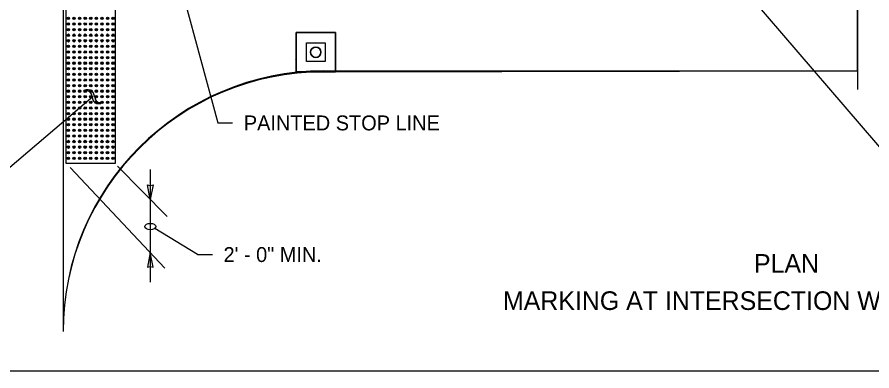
# Model space of a CAD drawing. Extents: x 99862 to 103151, y 100000 to 102076.
# Drawn here: x 100350 to 101268, y 100000 to 100380 of the extents above; entities that cross this region are included whole.
import ezdxf

# ---------------------------------------------------------------- set-up
doc = ezdxf.new("R2010")
doc.units = 0
for name, color, linetype in [('Level 1', 7, 'Continuous'), ('Level 15', 7, 'Continuous'), ('Level 2', 7, 'Continuous'), ('Level 20', 7, 'Continuous'), ('Level 22', 7, 'Continuous'), ('Level 3', 7, 'Continuous'), ('Level 5', 7, 'Continuous')]:
    doc.layers.add(name, color=color, linetype=linetype)

msp = doc.modelspace()

# ---------------------------------------------------------------- linework, layer by layer
at = {"layer": 'Level 1'}
for points in [[(99862, 99999.5), (103151, 99999.5), (103151, 102075.5), (99862, 102075.5)], [(100649.56, 100362.98), (100691.88, 100362.98), (100691.88, 100320.94), (100649.56, 100320.94)], [(100660.76, 100351.9), (100680.76, 100351.9), (100680.76, 100331.9), (100660.76, 100331.9)]]:
    msp.add_lwpolyline(points, close=True, dxfattribs=at)
for points in [[(100649.56, 100362.98), (100649.56, 100320.94), (100691.88, 100320.94), (100691.88, 100362.98), (100649.56, 100362.98)], [(100660.76, 100331.9), (100660.76, 100351.9), (100680.76, 100351.9), (100680.76, 100331.9), (100660.76, 100331.9)]]:
    msp.add_lwpolyline(points, dxfattribs=at)
msp.add_circle((100670.76, 100341.9), 5.59, dxfattribs=at)
at = {"layer": 'Level 15'}
for p, q in [((100507.67, 100479.69), (100565.51, 100265.94)), ((101089.52, 100457.2), (101313.09, 100196.3)), ((100422.68, 100300.39), (100424.27, 100301.77)), ((100425.11, 100300.33), (100422.68, 100300.39)), ((100424.27, 100301.77), (100426.26, 100301.9)), ((100426.81, 100300.03), (100425.11, 100300.33)), ((100426.26, 100301.9), (100428.03, 100301.6)), ((100428.05, 100299.45), (100426.81, 100300.03)), ((100428.03, 100301.6), (100429.57, 100300.87)), ((100429.05, 100298.58), (100428.05, 100299.45)), ((100430.02, 100296.92), (100429.05, 100298.58)), ((100429.57, 100300.87), (100430.88, 100299.7)), ((100430.88, 100299.7), (100432.29, 100297.37)), ((100431.78, 100294.2), (100329.7, 100207.59)), ((100430.73, 100294.47), (100430.02, 100296.92)), ((100431.77, 100290.51), (100430.73, 100294.47)), ((100433.09, 100288.43), (100431.77, 100290.51)), ((100432.29, 100297.37), (100433.49, 100293.12)), ((100433.49, 100293.12), (100434.16, 100290.79)), ((100434.16, 100290.79), (100434.95, 100289.51)), ((100434.95, 100289.51), (100436.06, 100288.63)), ((100434.33, 100287.32), (100433.09, 100288.43)), ((100435.79, 100286.63), (100434.33, 100287.32)), ((100437.54, 100286.32), (100435.79, 100286.63)), ((100436.06, 100288.63), (100437.59, 100288.04)), ((100439.69, 100286.37), (100437.54, 100286.32)), ((100437.59, 100288.04), (100441.28, 100287.76)), ((100441.28, 100287.76), (100439.68, 100286.37)), ((100565.51, 100265.94), (100581.51, 100265.94)), ((100407.2, 100218.06), (100508.8, 100109.97)), ((100457.85, 100219.34), (100511.1, 100165.26)), ((100493.13, 100216.07), (100493.13, 100184.21)), ((100493.13, 100183.61), (100493.13, 100125.5)), ((100543.71, 100124.51), (100497.79, 100152.56)), ((100493.13, 100126.59), (100493.13, 100094.73)), ((100543.71, 100124.51), (100559.71, 100124.51))]:
    msp.add_line(p, q, dxfattribs=at)
msp.add_lwpolyline([(101252.33, 100621.81), (101252.33, 100477.35), (101267.81, 100477.35), (101236.84, 100446.37), (101252.33, 100446.37), (101252.33, 100301.81)], dxfattribs=at)
for points in [[(100493.13, 100183.61), (100490.04, 100199.34), (100493.13, 100198.61), (100496.21, 100199.34)], [(100493.13, 100126.59), (100490.04, 100110.86), (100493.13, 100111.59), (100496.21, 100110.86)]]:
    msp.add_lwpolyline(points, close=True, dxfattribs=at)
msp.add_ellipse((100493.13, 100154.56), major_axis=(-6, 0), ratio=0.57735, dxfattribs=at)
at = {"layer": 'Level 2'}
for p, q in [((100399.47, 100881.81), (100399.47, 100041.81)), ((100399.47, 100881.81), (100399.47, 100041.81)), ((100679.47, 100321.81), (101252.2, 100321.81)), ((100679.47, 100320.79), (101252.2, 100321.81)), ((100679.47, 100321.81), (101251.39, 100321.81))]:
    msp.add_line(p, q, dxfattribs=at)
msp.add_lwpolyline([(101252.2, 100321.81), (101252.2, 100446.2), (101236.71, 100446.2), (101240.44, 100449.93)], dxfattribs=at)
for centre, radius, start, end in [((100679.47, 100041.81), 280, 90, 180), ((100678.97, 100041.3), 279.49, 89.89566, 179.89566)]:
    msp.add_arc(centre, radius, start, end, dxfattribs=at)
at = {"layer": 'Level 22'}
msp.add_line((100648.58, 100334.27), (100648.58, 100334.27), dxfattribs=at)
at = {"layer": 'Level 3'}
for start, end in [(0, 180), (180, 0)]:
    msp.add_arc((100670.76, 100341.9), 5.59, start, end, dxfattribs=at)
at = {"layer": 'Level 5'}
for p, q in [((100402.9, 100222.47), (100402.9, 100446.36)), ((100455.2, 100446.36), (100455.2, 100222.47)), ((100455.2, 100222.47), (100402.9, 100222.47))]:
    msp.add_line(p, q, dxfattribs=at)
for centre, major_axis in [((100405.21, 100378.25), (0, 1.31)), ((100405.21, 100372.23), (0, 1.31)), ((100405.17, 100378.25), (0, -0.755)), ((100405.17, 100372.23), (0, -0.755)), ((100411.21, 100378.25), (0, 1.31)), ((100411.21, 100372.23), (0, 1.31)), ((100411.17, 100378.25), (0, -0.755)), ((100411.17, 100372.23), (0, -0.755)), ((100417.21, 100378.25), (0, 1.31)), ((100417.21, 100372.23), (0, 1.31)), ((100417.17, 100378.25), (0, -0.755)), ((100417.17, 100372.23), (0, -0.755)), ((100423.21, 100378.25), (0, 1.31)), ((100423.21, 100372.23), (0, 1.31)), ((100423.17, 100378.25), (0, -0.755)), ((100423.17, 100372.23), (0, -0.755)), ((100429.21, 100378.25), (0, 1.31)), ((100429.21, 100372.23), (0, 1.31)), ((100429.17, 100378.25), (0, -0.755)), ((100429.17, 100372.23), (0, -0.755)), ((100435.21, 100378.25), (0, 1.31)), ((100435.21, 100372.23), (0, 1.31)), ((100435.17, 100378.25), (0, -0.755)), ((100435.17, 100372.23), (0, -0.755)), ((100441.21, 100378.25), (0, 1.31)), ((100441.21, 100372.23), (0, 1.31)), ((100441.17, 100378.25), (0, -0.755)), ((100441.17, 100372.23), (0, -0.755)), ((100447.21, 100378.25), (0, 1.31)), ((100447.21, 100372.23), (0, 1.31)), ((100447.17, 100378.25), (0, -0.755)), ((100447.17, 100372.23), (0, -0.755)), ((100453.21, 100378.25), (0, 1.31)), ((100453.21, 100372.23), (0, 1.31)), ((100453.17, 100378.25), (0, -0.755)), ((100453.17, 100372.23), (0, -0.755)), ((100405.21, 100366.22), (0, 1.31)), ((100405.17, 100366.22), (0, -0.755)), ((100411.21, 100366.22), (0, 1.31)), ((100411.17, 100366.22), (0, -0.755)), ((100417.21, 100366.22), (0, 1.31)), ((100417.17, 100366.22), (0, -0.755)), ((100423.21, 100366.22), (0, 1.31)), ((100423.17, 100366.22), (0, -0.755)), ((100429.21, 100366.22), (0, 1.31)), ((100429.17, 100366.22), (0, -0.755)), ((100435.21, 100366.22), (0, 1.31)), ((100435.17, 100366.22), (0, -0.755)), ((100441.21, 100366.22), (0, 1.31)), ((100441.17, 100366.22), (0, -0.755)), ((100447.21, 100366.22), (0, 1.31)), ((100447.17, 100366.22), (0, -0.755)), ((100453.21, 100366.22), (0, 1.31)), ((100453.17, 100366.22), (0, -0.755)), ((100405.21, 100360.2), (0, 1.31)), ((100405.21, 100354.19), (0, 1.31)), ((100405.17, 100360.2), (0, -0.755)), ((100405.17, 100354.19), (0, -0.755)), ((100411.21, 100360.2), (0, 1.31)), ((100411.21, 100354.19), (0, 1.31)), ((100411.17, 100360.2), (0, -0.755)), ((100411.17, 100354.19), (0, -0.755)), ((100417.21, 100360.2), (0, 1.31)), ((100417.21, 100354.19), (0, 1.31)), ((100417.17, 100360.2), (0, -0.755)), ((100417.17, 100354.19), (0, -0.755)), ((100423.21, 100360.2), (0, 1.31)), ((100423.21, 100354.19), (0, 1.31)), ((100423.17, 100360.2), (0, -0.755)), ((100423.17, 100354.19), (0, -0.755)), ((100429.21, 100360.2), (0, 1.31)), ((100429.21, 100354.19), (0, 1.31)), ((100429.17, 100360.2), (0, -0.755)), ((100429.17, 100354.19), (0, -0.755)), ((100435.21, 100360.2), (0, 1.31)), ((100435.21, 100354.19), (0, 1.31)), ((100435.17, 100360.2), (0, -0.755)), ((100435.17, 100354.19), (0, -0.755)), ((100441.21, 100360.2), (0, 1.31)), ((100441.21, 100354.19), (0, 1.31)), ((100441.17, 100360.2), (0, -0.755)), ((100441.17, 100354.19), (0, -0.755)), ((100447.21, 100360.2), (0, 1.31)), ((100447.21, 100354.19), (0, 1.31)), ((100447.17, 100360.2), (0, -0.755)), ((100447.17, 100354.19), (0, -0.755)), ((100453.21, 100360.2), (0, 1.31)), ((100453.21, 100354.19), (0, 1.31)), ((100453.17, 100360.2), (0, -0.755)), ((100453.17, 100354.19), (0, -0.755)), ((100405.21, 100348.18), (0, 1.31)), ((100405.17, 100348.18), (0, -0.755)), ((100411.21, 100348.18), (0, 1.31)), ((100411.17, 100348.18), (0, -0.755)), ((100417.21, 100348.18), (0, 1.31)), ((100417.17, 100348.18), (0, -0.755)), ((100423.21, 100348.18), (0, 1.31)), ((100423.17, 100348.18), (0, -0.755)), ((100429.21, 100348.18), (0, 1.31)), ((100429.17, 100348.18), (0, -0.755)), ((100435.21, 100348.18), (0, 1.31)), ((100435.17, 100348.18), (0, -0.755)), ((100441.21, 100348.18), (0, 1.31)), ((100441.17, 100348.18), (0, -0.755)), ((100447.21, 100348.18), (0, 1.31)), ((100447.17, 100348.18), (0, -0.755)), ((100453.21, 100348.18), (0, 1.31)), ((100453.17, 100348.18), (0, -0.755)), ((100405.21, 100342.16), (0, 1.31)), ((100405.21, 100336.15), (0, 1.31)), ((100405.17, 100342.16), (0, -0.755)), ((100405.17, 100336.15), (0, -0.755)), ((100411.21, 100342.16), (0, 1.31)), ((100411.21, 100336.15), (0, 1.31)), ((100411.17, 100342.16), (0, -0.755)), ((100411.17, 100336.15), (0, -0.755)), ((100417.21, 100342.16), (0, 1.31)), ((100417.21, 100336.15), (0, 1.31)), ((100417.17, 100342.16), (0, -0.755)), ((100417.17, 100336.15), (0, -0.755)), ((100423.21, 100342.16), (0, 1.31)), ((100423.21, 100336.15), (0, 1.31)), ((100423.17, 100342.16), (0, -0.755)), ((100423.17, 100336.15), (0, -0.755)), ((100429.21, 100342.16), (0, 1.31)), ((100429.21, 100336.15), (0, 1.31)), ((100429.17, 100342.16), (0, -0.755)), ((100429.17, 100336.15), (0, -0.755)), ((100435.21, 100342.16), (0, 1.31)), ((100435.21, 100336.15), (0, 1.31)), ((100435.17, 100342.16), (0, -0.755)), ((100435.17, 100336.15), (0, -0.755)), ((100441.21, 100342.16), (0, 1.31)), ((100441.21, 100336.15), (0, 1.31)), ((100441.17, 100342.16), (0, -0.755)), ((100441.17, 100336.15), (0, -0.755)), ((100447.21, 100342.16), (0, 1.31)), ((100447.21, 100336.15), (0, 1.31)), ((100447.17, 100342.16), (0, -0.755)), ((100447.17, 100336.15), (0, -0.755)), ((100453.21, 100342.16), (0, 1.31)), ((100453.21, 100336.15), (0, 1.31)), ((100453.17, 100342.16), (0, -0.755)), ((100453.17, 100336.15), (0, -0.755)), ((100405.21, 100330.13), (0, 1.31)), ((100405.17, 100330.13), (0, -0.755)), ((100411.21, 100330.13), (0, 1.31)), ((100411.17, 100330.13), (0, -0.755)), ((100417.21, 100330.13), (0, 1.31)), ((100417.17, 100330.13), (0, -0.755)), ((100423.21, 100330.13), (0, 1.31)), ((100423.17, 100330.13), (0, -0.755)), ((100429.21, 100330.13), (0, 1.31)), ((100429.17, 100330.13), (0, -0.755)), ((100435.21, 100330.13), (0, 1.31)), ((100435.17, 100330.13), (0, -0.755)), ((100441.21, 100330.13), (0, 1.31)), ((100441.17, 100330.13), (0, -0.755)), ((100447.21, 100330.13), (0, 1.31)), ((100447.17, 100330.13), (0, -0.755)), ((100453.21, 100330.13), (0, 1.31)), ((100453.17, 100330.13), (0, -0.755)), ((100405.21, 100324.12), (0, 1.31)), ((100405.21, 100318.11), (0, 1.31)), ((100405.17, 100324.12), (0, -0.755)), ((100405.17, 100318.11), (0, -0.755)), ((100411.21, 100324.12), (0, 1.31)), ((100411.21, 100318.11), (0, 1.31)), ((100411.17, 100324.12), (0, -0.755)), ((100411.17, 100318.11), (0, -0.755)), ((100417.21, 100324.12), (0, 1.31)), ((100417.21, 100318.11), (0, 1.31)), ((100417.17, 100324.12), (0, -0.755)), ((100417.17, 100318.11), (0, -0.755)), ((100423.21, 100324.12), (0, 1.31)), ((100423.21, 100318.11), (0, 1.31)), ((100423.17, 100324.12), (0, -0.755)), ((100423.17, 100318.11), (0, -0.755)), ((100429.21, 100324.12), (0, 1.31)), ((100429.21, 100318.11), (0, 1.31)), ((100429.17, 100324.12), (0, -0.755)), ((100429.17, 100318.11), (0, -0.755)), ((100435.21, 100324.12), (0, 1.31)), ((100435.21, 100318.11), (0, 1.31)), ((100435.17, 100324.12), (0, -0.755)), ((100435.17, 100318.11), (0, -0.755)), ((100441.21, 100324.12), (0, 1.31)), ((100441.21, 100318.11), (0, 1.31)), ((100441.17, 100324.12), (0, -0.755)), ((100441.17, 100318.11), (0, -0.755)), ((100447.21, 100324.12), (0, 1.31)), ((100447.21, 100318.11), (0, 1.31)), ((100447.17, 100324.12), (0, -0.755)), ((100447.17, 100318.11), (0, -0.755)), ((100453.21, 100324.12), (0, 1.31)), ((100453.21, 100318.11), (0, 1.31)), ((100453.17, 100324.12), (0, -0.755)), ((100453.17, 100318.11), (0, -0.755)), ((100405.21, 100312.09), (0, 1.31)), ((100405.17, 100312.09), (0, -0.755)), ((100411.21, 100312.09), (0, 1.31)), ((100411.17, 100312.09), (0, -0.755)), ((100417.21, 100312.09), (0, 1.31)), ((100417.17, 100312.09), (0, -0.755)), ((100423.21, 100312.09), (0, 1.31)), ((100423.17, 100312.09), (0, -0.755)), ((100429.21, 100312.09), (0, 1.31)), ((100429.17, 100312.09), (0, -0.755)), ((100435.21, 100312.09), (0, 1.31)), ((100435.17, 100312.09), (0, -0.755)), ((100441.21, 100312.09), (0, 1.31)), ((100441.17, 100312.09), (0, -0.755)), ((100447.21, 100312.09), (0, 1.31)), ((100447.17, 100312.09), (0, -0.755)), ((100453.21, 100312.09), (0, 1.31)), ((100453.17, 100312.09), (0, -0.755)), ((100405.21, 100306.08), (0, 1.31)), ((100405.21, 100300.07), (0, 1.31)), ((100405.17, 100306.08), (0, -0.755)), ((100405.17, 100300.07), (0, -0.755)), ((100411.21, 100306.08), (0, 1.31)), ((100411.21, 100300.07), (0, 1.31)), ((100411.17, 100306.08), (0, -0.755)), ((100411.17, 100300.07), (0, -0.755)), ((100417.21, 100306.08), (0, 1.31)), ((100417.21, 100300.07), (0, 1.31)), ((100417.17, 100306.08), (0, -0.755)), ((100417.17, 100300.07), (0, -0.755)), ((100423.21, 100306.08), (0, 1.31)), ((100423.21, 100300.07), (0, 1.31)), ((100423.17, 100306.08), (0, -0.755)), ((100423.17, 100300.07), (0, -0.755)), ((100429.21, 100306.08), (0, 1.31)), ((100429.21, 100300.07), (0, 1.31)), ((100429.17, 100306.08), (0, -0.755)), ((100429.17, 100300.07), (0, -0.755)), ((100435.21, 100306.08), (0, 1.31)), ((100435.21, 100300.07), (0, 1.31)), ((100435.17, 100306.08), (0, -0.755)), ((100435.17, 100300.07), (0, -0.755)), ((100441.21, 100306.08), (0, 1.31)), ((100441.21, 100300.07), (0, 1.31)), ((100441.17, 100306.08), (0, -0.755)), ((100441.17, 100300.07), (0, -0.755)), ((100447.21, 100306.08), (0, 1.31)), ((100447.21, 100300.07), (0, 1.31)), ((100447.17, 100306.08), (0, -0.755)), ((100447.17, 100300.07), (0, -0.755)), ((100453.21, 100306.08), (0, 1.31)), ((100453.21, 100300.07), (0, 1.31)), ((100453.17, 100306.08), (0, -0.755)), ((100453.17, 100300.07), (0, -0.755)), ((100405.21, 100294.05), (0, 1.31)), ((100405.21, 100288.04), (0, 1.31)), ((100405.17, 100294.05), (0, -0.755)), ((100411.21, 100294.05), (0, 1.31)), ((100411.21, 100288.04), (0, 1.31)), ((100411.17, 100294.05), (0, -0.755)), ((100417.21, 100294.05), (0, 1.31)), ((100417.21, 100288.04), (0, 1.31)), ((100417.17, 100294.05), (0, -0.755)), ((100423.21, 100294.05), (0, 1.31)), ((100423.21, 100288.04), (0, 1.31)), ((100423.17, 100294.05), (0, -0.755)), ((100429.21, 100294.05), (0, 1.31)), ((100429.21, 100288.04), (0, 1.31)), ((100429.17, 100294.05), (0, -0.755)), ((100435.21, 100294.05), (0, 1.31)), ((100435.21, 100288.04), (0, 1.31)), ((100435.17, 100294.05), (0, -0.755)), ((100441.21, 100294.05), (0, 1.31)), ((100441.21, 100288.04), (0, 1.31)), ((100441.17, 100294.05), (0, -0.755)), ((100447.21, 100294.05), (0, 1.31)), ((100447.21, 100288.04), (0, 1.31)), ((100447.17, 100294.05), (0, -0.755)), ((100453.21, 100294.05), (0, 1.31)), ((100453.21, 100288.04), (0, 1.31)), ((100453.17, 100294.05), (0, -0.755)), ((100405.21, 100282.02), (0, 1.31)), ((100405.17, 100288.04), (0, -0.755)), ((100405.17, 100282.02), (0, -0.755)), ((100411.21, 100282.02), (0, 1.31)), ((100411.17, 100288.04), (0, -0.755)), ((100411.17, 100282.02), (0, -0.755)), ((100417.21, 100282.02), (0, 1.31)), ((100417.17, 100288.04), (0, -0.755)), ((100417.17, 100282.02), (0, -0.755)), ((100423.21, 100282.02), (0, 1.31)), ((100423.17, 100288.04), (0, -0.755)), ((100423.17, 100282.02), (0, -0.755)), ((100429.21, 100282.02), (0, 1.31)), ((100429.17, 100288.04), (0, -0.755)), ((100429.17, 100282.02), (0, -0.755)), ((100435.21, 100282.02), (0, 1.31)), ((100435.17, 100288.04), (0, -0.755)), ((100435.17, 100282.02), (0, -0.755)), ((100441.21, 100282.02), (0, 1.31)), ((100441.17, 100288.04), (0, -0.755)), ((100441.17, 100282.02), (0, -0.755)), ((100447.21, 100282.02), (0, 1.31)), ((100447.17, 100288.04), (0, -0.755)), ((100447.17, 100282.02), (0, -0.755)), ((100453.21, 100282.02), (0, 1.31)), ((100453.17, 100288.04), (0, -0.755)), ((100453.17, 100282.02), (0, -0.755)), ((100405.21, 100276.01), (0, 1.31)), ((100405.21, 100270), (0, 1.31)), ((100405.17, 100276.01), (0, -0.755)), ((100411.21, 100276.01), (0, 1.31)), ((100411.21, 100270), (0, 1.31)), ((100411.17, 100276.01), (0, -0.755)), ((100417.21, 100276.01), (0, 1.31)), ((100417.21, 100270), (0, 1.31)), ((100417.17, 100276.01), (0, -0.755)), ((100423.21, 100276.01), (0, 1.31)), ((100423.21, 100270), (0, 1.31)), ((100423.17, 100276.01), (0, -0.755)), ((100429.21, 100276.01), (0, 1.31)), ((100429.21, 100270), (0, 1.31)), ((100429.17, 100276.01), (0, -0.755)), ((100435.21, 100276.01), (0, 1.31)), ((100435.21, 100270), (0, 1.31)), ((100435.17, 100276.01), (0, -0.755)), ((100441.21, 100276.01), (0, 1.31)), ((100441.21, 100270), (0, 1.31)), ((100441.17, 100276.01), (0, -0.755)), ((100447.21, 100276.01), (0, 1.31)), ((100447.21, 100270), (0, 1.31)), ((100447.17, 100276.01), (0, -0.755)), ((100453.21, 100276.01), (0, 1.31)), ((100453.21, 100270), (0, 1.31)), ((100453.17, 100276.01), (0, -0.755)), ((100405.21, 100263.98), (0, 1.31)), ((100405.17, 100270), (0, -0.755)), ((100405.17, 100263.98), (0, -0.755)), ((100411.21, 100263.98), (0, 1.31)), ((100411.17, 100270), (0, -0.755)), ((100411.17, 100263.98), (0, -0.755)), ((100417.21, 100263.98), (0, 1.31)), ((100417.17, 100270), (0, -0.755)), ((100417.17, 100263.98), (0, -0.755)), ((100423.21, 100263.98), (0, 1.31)), ((100423.17, 100270), (0, -0.755)), ((100423.17, 100263.98), (0, -0.755)), ((100429.21, 100263.98), (0, 1.31)), ((100429.17, 100270), (0, -0.755)), ((100429.17, 100263.98), (0, -0.755)), ((100435.21, 100263.98), (0, 1.31)), ((100435.17, 100270), (0, -0.755)), ((100435.17, 100263.98), (0, -0.755)), ((100441.21, 100263.98), (0, 1.31)), ((100441.17, 100270), (0, -0.755)), ((100441.17, 100263.98), (0, -0.755)), ((100447.21, 100263.98), (0, 1.31)), ((100447.17, 100270), (0, -0.755)), ((100447.17, 100263.98), (0, -0.755)), ((100453.21, 100263.98), (0, 1.31)), ((100453.17, 100270), (0, -0.755)), ((100453.17, 100263.98), (0, -0.755)), ((100405.17, 100251.97), (0, 1.31)), ((100405.21, 100257.97), (0, 1.31)), ((100405.13, 100251.97), (0, -0.755)), ((100405.17, 100257.97), (0, -0.755)), ((100411.17, 100251.97), (0, 1.31)), ((100411.21, 100257.97), (0, 1.31)), ((100411.13, 100251.97), (0, -0.755)), ((100411.17, 100257.97), (0, -0.755)), ((100417.17, 100251.97), (0, 1.31)), ((100417.21, 100257.97), (0, 1.31)), ((100417.13, 100251.97), (0, -0.755)), ((100417.17, 100257.97), (0, -0.755)), ((100423.17, 100251.97), (0, 1.31)), ((100423.21, 100257.97), (0, 1.31)), ((100423.13, 100251.97), (0, -0.755)), ((100423.17, 100257.97), (0, -0.755)), ((100429.17, 100251.97), (0, 1.31)), ((100429.21, 100257.97), (0, 1.31)), ((100429.13, 100251.97), (0, -0.755)), ((100429.17, 100257.97), (0, -0.755)), ((100435.17, 100251.97), (0, 1.31)), ((100435.21, 100257.97), (0, 1.31)), ((100435.13, 100251.97), (0, -0.755)), ((100435.17, 100257.97), (0, -0.755)), ((100441.17, 100251.97), (0, 1.31)), ((100441.21, 100257.97), (0, 1.31)), ((100441.13, 100251.97), (0, -0.755)), ((100441.17, 100257.97), (0, -0.755)), ((100447.17, 100251.97), (0, 1.31)), ((100447.21, 100257.97), (0, 1.31)), ((100447.13, 100251.97), (0, -0.755)), ((100447.17, 100257.97), (0, -0.755)), ((100453.17, 100251.97), (0, 1.31)), ((100453.21, 100257.97), (0, 1.31)), ((100453.13, 100251.97), (0, -0.755)), ((100453.17, 100257.97), (0, -0.755)), ((100405.17, 100245.95), (0, 1.31)), ((100405.13, 100245.95), (0, -0.755)), ((100411.17, 100245.95), (0, 1.31)), ((100411.13, 100245.95), (0, -0.755)), ((100417.17, 100245.95), (0, 1.31)), ((100417.13, 100245.95), (0, -0.755)), ((100423.17, 100245.95), (0, 1.31)), ((100423.13, 100245.95), (0, -0.755)), ((100429.17, 100245.95), (0, 1.31)), ((100429.13, 100245.95), (0, -0.755)), ((100435.17, 100245.95), (0, 1.31)), ((100435.13, 100245.95), (0, -0.755)), ((100441.17, 100245.95), (0, 1.31)), ((100441.13, 100245.95), (0, -0.755)), ((100447.17, 100245.95), (0, 1.31)), ((100447.13, 100245.95), (0, -0.755)), ((100453.17, 100245.95), (0, 1.31)), ((100453.13, 100245.95), (0, -0.755)), ((100405.17, 100239.94), (0, 1.31)), ((100405.17, 100233.93), (0, 1.31)), ((100405.13, 100239.94), (0, -0.755)), ((100405.13, 100233.93), (0, -0.755)), ((100411.17, 100239.94), (0, 1.31)), ((100411.17, 100233.93), (0, 1.31)), ((100411.13, 100239.94), (0, -0.755)), ((100411.13, 100233.93), (0, -0.755)), ((100417.17, 100239.94), (0, 1.31)), ((100417.17, 100233.93), (0, 1.31)), ((100417.13, 100239.94), (0, -0.755)), ((100417.13, 100233.93), (0, -0.755)), ((100423.17, 100239.94), (0, 1.31)), ((100423.17, 100233.93), (0, 1.31)), ((100423.13, 100239.94), (0, -0.755)), ((100423.13, 100233.93), (0, -0.755)), ((100429.17, 100239.94), (0, 1.31)), ((100429.17, 100233.93), (0, 1.31)), ((100429.13, 100239.94), (0, -0.755)), ((100429.13, 100233.93), (0, -0.755)), ((100435.17, 100239.94), (0, 1.31)), ((100435.17, 100233.93), (0, 1.31)), ((100435.13, 100239.94), (0, -0.755)), ((100435.13, 100233.93), (0, -0.755)), ((100441.17, 100239.94), (0, 1.31)), ((100441.17, 100233.93), (0, 1.31)), ((100441.13, 100239.94), (0, -0.755)), ((100441.13, 100233.93), (0, -0.755)), ((100447.17, 100239.94), (0, 1.31)), ((100447.17, 100233.93), (0, 1.31)), ((100447.13, 100239.94), (0, -0.755)), ((100447.13, 100233.93), (0, -0.755)), ((100453.17, 100239.94), (0, 1.31)), ((100453.17, 100233.93), (0, 1.31)), ((100453.13, 100239.94), (0, -0.755)), ((100453.13, 100233.93), (0, -0.755)), ((100405.17, 100227.91), (0, 1.31)), ((100405.13, 100227.91), (0, -0.755)), ((100411.17, 100227.91), (0, 1.31)), ((100411.13, 100227.91), (0, -0.755)), ((100417.17, 100227.91), (0, 1.31)), ((100417.13, 100227.91), (0, -0.755)), ((100423.17, 100227.91), (0, 1.31)), ((100423.13, 100227.91), (0, -0.755)), ((100429.17, 100227.91), (0, 1.31)), ((100429.13, 100227.91), (0, -0.755)), ((100435.17, 100227.91), (0, 1.31)), ((100435.13, 100227.91), (0, -0.755)), ((100441.17, 100227.91), (0, 1.31)), ((100441.13, 100227.91), (0, -0.755)), ((100447.17, 100227.91), (0, 1.31)), ((100447.13, 100227.91), (0, -0.755)), ((100453.17, 100227.91), (0, 1.31)), ((100453.13, 100227.91), (0, -0.755))]:
    msp.add_ellipse(centre, major_axis=major_axis, ratio=0.997648, dxfattribs=at)

# ---------------------------------------------------------------- texts
at = {"layer": 'Level 20'}
for s, height, p in [('PAINTED STOP LINE', 16, (100593.51, 100257.94)), ('2\' - 0" MIN.', 16, (100571.71, 100116.51)), ('PLAN', 20, (101141.19, 100105)), ('MARKING AT INTERSECTION WITH ROADWAY', 20, (100871.72, 100065))]:
    msp.add_text(s, height=height, dxfattribs=at).set_placement(p)

doc.saveas('drawing.dxf')
